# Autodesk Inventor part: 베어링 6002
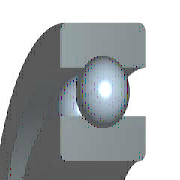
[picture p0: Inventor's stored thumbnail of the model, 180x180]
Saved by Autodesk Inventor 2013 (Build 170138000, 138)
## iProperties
IsCustomPart: 0
Created: 2015-10
Part Number: 베어링 6002
Material: 강, 연강
Description: 깊은 그루브 볼 베어링
Document SubType Name: Modeling
Standard: KS B 2023
Designer: mdu
Standards Organization: KS
Language: ko-KR
Size Designation: 6002 - 15 x 32 x 9
Categories: <MemberInstance><Categories><Category DisplayName="샤프트 부품" InternalName="7f7aeb1f-a693-4053-b835-cee3144e0d98" Mnemonic="SHFT"><Category DisplayName="베어링" Inter
Density: 1 g/cm^3
Author: mdu
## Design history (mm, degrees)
sketch "스케치" dims "d0" = 4.42 (= -0.26 x WD + 0.26 x BD)
  geometry: L1 (2.29, 11.75)-(6.71, 11.75); L2 (4.5, 11.75)-(4.5, 9.54); L3 (4.5, 11.75)-(4.5, 13.96); L4 (2.858, 10.271)-(0, 10.271); L5 (0, 7.5)-(9, 7.5); L6 (2.858, 13.229)-(0, 13.229); L7 (0, 16)-(9, 16); L8 (9, 7.5)-(9, 10.271); L9 (6.142, 10.271)-(9, 10.271); L10 (6.142, 13.229)-(9, 13.229); L11 (9, 16)-(9, 13.229); L12 (-1.4, 0)-(8.4, 0) reference; L13 (0, -0.3)-(0, 5.3) reference
  constraints: 22 end point, 4 point on line, 2 collinear, 2 perpendicular, 2 symmetric about line, 1 midpoint, 1 parallel, 14 other
  dimensions: "d9" = 15 diameter of L5 L12 (= WD); "d11" = 32 diameter of L7 L12 (= BD); "d12" = 9 distance between parallel lines of L8 L13 (= KB); "d13" = 20.542 diameter of L9 L12 (= 0.326 x BD + 0.674 x WD)
revolve "본체" stored, may be unused: angle "d6" = 90 deg
revolve "볼" stored, may be unused: angle "d7" = 90 deg
pattern_circular "IDS_ARRAYBALL[SIMPL:T]" dims angle "d3" = 360 deg
body "Solid1"
fillet "모깎기1" dims "d1" = 0.3 (= KRS)
other parameters: "WD" = 15 [user parameter; used in 5 equation terms], "BD" = 32 [user parameter; used in 5 equation terms], "KB" = 9 [user parameter; used in 1 equation term], "KRS" = 0.3 [user parameter; used in 1 equation term], "d4" = 0, "d5" = 0, "d8" = 0, "d14" = 0, "d15" = 0, "BBA" = 0 [user parameter], "BC0" = 2850000 [user parameter], "BC" = 5590000 [user parameter], "BR" = 16 (= 0.5 x BD) [user parameter], "WR" = 7.5 (= 0.5 x WD) [user parameter]
